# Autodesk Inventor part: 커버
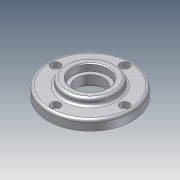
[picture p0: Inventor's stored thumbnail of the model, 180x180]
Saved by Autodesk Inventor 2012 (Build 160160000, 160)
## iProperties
Company: 한국ATC센터
Created: 2013-01
Part Number: 커버
Document SubType Name: Modeling
Designer: KYOUNG IL JANG
Density: 1 g/cm^3
Material: 기본값
Author: KYOUNG IL JANG
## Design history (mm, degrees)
sketch "스케치1"
  geometry: C1 r 31 at (0, 0) reference; C2 r 50 at (0, 0); 1 further point
  constraints: 1 centre point, 1 coincident
  dimensions: "d41" = 100 diameter of C2
extrude "돌출1" new body sketch "스케치1" distance "d0" = 12; taper "d1" = 0 deg
sketch "스케치2"
  geometry: C1 r 30 at (0, 0); 1 further point
  constraints: 1 centre point, 1 coincident
  dimensions: "d2" = 60 diameter of C1
extrude "돌출2" join sketch "스케치2" distance "d3" = 8; taper "d4" = 0 deg
fillet "모깎기1" dims "d5" = 3
sketch "스케치3" dims "d42" = 82
  geometry: 3 further points
  constraints: 2 vertical alignment, 1 coincident, 2 other
hole "구멍1" sketch "스케치3" at (0, 41) diameter "d6" = 6.6; stored, may be unused: countersink angle "d10" = 90 deg, drill point angle "d12" = 118 deg; dims "d7" = 6, "d8" = 11, "d9" = 6.5, "d11" = 8
hole "구멍2" diameter "d18" = 33; stored, may be unused: countersink angle "d22" = 90 deg, drill point angle "d24" = 118 deg; dims "d16" = 10, "d17" = 10, "d19" = 6, "d20" = 42, "d21" = 8.5, "d23" = 8
sketch "스케치4"
  geometry: C1 r 31 at (0, 0) reference; C2 r 22.5 at (0, 0); 1 further point
  constraints: 1 centre point, 1 coincident
  dimensions: "d43" = 45 diameter of C2
extrude "돌출3" join sketch "스케치4" distance "d25" = 6; taper "d26" = 0 deg
hole "구멍3" diameter "d29" = 50; stored, may be unused: countersink angle "d33" = 90 deg, drill point angle "d35" = 0 deg; dims "d27" = 10, "d28" = 10, "d30" = 6, "d31" = 42, "d32" = 8.5, "d34" = 7
fillet "모깎기2" dims "d36" = 3, "d37" = 0.3
chamfer "모따기1" distance "d38" = 1; stored, may be unused: second distance "d39" = 2, angle "d40" = 45 deg
node "솔리드1"
pattern_circular "원형 패턴1" dims angle "d14" = 360 deg
node "참조9"
node "참조11"
